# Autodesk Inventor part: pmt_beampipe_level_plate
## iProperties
Shininess: 64.0
Length Units: 11269
Angle Units: 11279
Time Units: 11290
Mass Units: 11283
Length Display Precision: 3
Angle Display Precision: 2
Compacted: True
Part Number: pmt_beampipe_level_plate
Document SubType Name: Modeling
Created: 2004-08
Designer: John Blackburn
Manufacturer: Standard
Standards Organization: Custom
Material: Aluminum-6061
Density: 0.0
Volumn: 0.0
Area: 0.0
PropertySet Name: Model Information
Control State: 0
Master: False
Checked Out: False
Author: John Blackburn
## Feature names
1. Extrusion1
2. Hole1
